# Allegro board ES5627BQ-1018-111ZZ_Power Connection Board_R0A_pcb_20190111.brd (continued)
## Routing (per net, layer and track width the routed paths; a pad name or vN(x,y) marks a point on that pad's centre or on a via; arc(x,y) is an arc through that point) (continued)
VMONITOR_3V3_EN: length 5.8
  TOP w0.127: R8.2 v2(84.75,29.54)
  TOP w0.381: R8.2 84.72,30.22 R7.2 C14.1 82.54,30.37 82.54,31.54 82.31,31.76 U1.7
  BOTTOM w0.127: v2(84.75,29.54) 85.06,29.23 v1(85.51,29.23)
VMONITOR_3V3_PG: length 8.7
  TOP w0.254: 79.07,30.79 79.07,28.73 CONN1.1 ; 79.07,30.79 R4.1 ; 79.07,30.79 79.56,30.79 81.18,32.41 U1.6
  BOTTOM w0.127: CONN1.1 78.39,28.53 v1(76.22,28.53)
VREG5_USB_VCC5P0: length 3.3
  TOP w0.254: U2.6 v2(74.48,40.38) 73.62,40.38 C41.1
  BOTTOM w0.127: v1(75.35,40.43) 74.53,40.43 v2(74.48,40.38)
VREG5_VSTB_3V3: length 6.6
  TOP w0.254: R4.2 C6.2 79.03,33.88 79.51,34.36 v2(80.43,34.36) U1.3
  BOTTOM w0.127: v2(80.43,34.36) 79.87,34.92 v1(79.87,35.48)
VSTB_3V3: length 18.7
  BOTTOM w0.381: C121.2 42.68,41.14 42.71,41.17 ; 40.65,41.24 40.6,41.19 C59.1 ; 41.67,41.34 41.69,41.32 C120.1
  BOTTOM w0.762: CONN20.18 41.35,50.88 ; CONN20.18 41.01,51.87 ; CONN20.18 40.01,49.55 ; CONN20.18 39.02,49.89 ; CONN20.18 41.01,49.89 ; 39.02,44.39 CONN20.6 ; CONN20.6 41.01,46.37 ; CONN20.6 40.01,46.71 ; CONN20.6 41.35,45.38 ; CONN20.6 40.01,44.05 ; CONN20.6 39.02,46.37 ; CONN20.6 41.01,44.39
  vias: v1(39.96,41.98)
VSTB_3V3_BODE: length 7.7
  TOP w0.127: v2(75.84,35.39) 75.84,35.71 76.12,35.99 R5.1
  TOP w0.254: U1.1 80.57,35.66 80.2,36.03 C9.1 R2.2 77.08,36.03 R5.1
  BOTTOM w0.127: v1(75.07,34.69) 75.14,34.69 v2(75.84,35.39)
VSTB_3V3_VIN: length 13.2
  TOP w0.381: R8.1 v2(86.6,30.24) ; C20.1 90.82,36.44 90.89,36.37 ; C19.1 89.77,36.29 89.8,36.26
  BOTTOM w0.381: v2(86.6,30.24) 86.6,35.02 v1(87.34,35.76) 87.56,35.98 v2(88.78,35.98) ; v2(93.04,35.44) 93.04,36.5 92.77,36.77 C22.1 92.09,36.77 91.82,36.5 v2(91.82,35.39)
N52288693: length 6.7
  TOP w0.254: U4.10 14.52,31.32 14.32,31.12 DB2.C 14.35,30.12 C91.1 v2(16.8,30.12) 17.5,30.12 D1.C
  BOTTOM w0.127: v2(16.8,30.12) 16.8,29.74 v1(16.44,29.38)
N55217970: length 5.1
  TOP w0.254: U7.3 v2(35.89,31.78)
  BOTTOM w0.127: v2(35.89,31.78) 35.55,31.44 v1(35.55,30.85)
  BOTTOM w0.254: v2(35.89,31.78) 36.64,31.78 R78.1 R79.1
N55218056: length 3
  TOP w0.254: U7.1 v2(36.83,33.68)
  BOTTOM w0.127: v1(36.83,34.56) v2(36.83,33.68)
  BOTTOM w0.254: C132.1 37.7,33.68 v2(36.83,33.68)
N55218105: length 2
  BOTTOM w0.127: v1(39.84,29.89) 39.86,29.91 R80.2
  BOTTOM w0.254: C133.2 R80.2
N55218124: length 4
  TOP w0.254: v2(41.59,31.74) 40.42,31.74 U7.4
  BOTTOM w0.127: v1(41.49,32.79) 41.59,32.68 v2(41.59,31.74)
  BOTTOM w0.254: R80.1 R81.1 v2(41.59,31.74)
N55219000: length 3.9
  TOP w0.254: U8.3 v2(73.45,26.7)
  BOTTOM w0.127: v1(73.95,27.35) 73.95,27.2 v2(73.45,26.7)
  BOTTOM w0.254: R84.1 72.65,26.92 R83.1 72.88,26.7 v2(73.45,26.7)
N55219084: length 3.5
  TOP w0.254: v2(73.47,24.73) 73.4,24.8 U8.1
  BOTTOM w0.127: v1(73.75,23.92) 73.75,24.45 v2(73.47,24.73)
  BOTTOM w0.254: v2(73.47,24.73) 73.4,24.8 72.39,24.8 C135.1
N55219133: length 2.1
  BOTTOM w0.127: v1(70.27,24.73) 70.37,24.83 C136.2
  BOTTOM w0.254: C136.2 70.34,25.8 R85.2
N55219143: length 4.1
  TOP w0.254: U8.4 v2(68.67,26.7)
  BOTTOM w0.127: v2(68.67,26.7) 68.27,26.7 v1(67.93,26.36)
  BOTTOM w0.254: R86.1 69.3,26.95 R85.1 69.31,26.7 v2(68.67,26.7)
N55250293: length 2.1
  BOTTOM w0.127: CB54.2 20.54,20.64 v1(20.64,20.54)
  BOTTOM w0.254: RB25.2 CB54.2

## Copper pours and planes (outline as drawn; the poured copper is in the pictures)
AGND_FPGA_1V2 on BOTTOM: 11.63,23.95 10.85,23.95 10.59,23.7 10.59,21.97 11.25,21.31 13.84,21.31 13.84,23.44 13.54,23.75 11.84,23.75
GND on TOP: 52.04,30.38 52.04,39.38 52.57,39.91 57.12,39.91 57.41,39.62 57.41,32.32 54.97,29.89 52.54,29.89
GND on TOP: 31.98,41.94 40.89,41.94 41.61,41.22 41.61,39.9 40.67,38.96 38.35,38.96 37.41,38.02 37.41,35.43 36.55,34.57 33.17,34.57 32.72,35.03 32.72,35.51 32.99,35.79 35.59,35.79 35.92,36.12 35.92,38.25 33.66,40.51 31.93,40.51 31.93,41.88
GND on TOP: 14.59,17.39 11.49,17.39 11.26,17.16 11.26,13.94 11.77,13.43 14.51,13.43 15.2,14.11 15.2,16.78
GND on TOP: 24.61,24.21 27.18,24.21 27.76,23.62 27.76,22.83 27.2,22.28 24.69,22.28 24.43,22.53 24.43,24.03
GND on TOP: 30.85,17.44 27.44,17.44 26.81,16.81 26.81,14.22 27.42,13.61 30.59,13.61 31.33,14.34 31.33,16.96
GND on TOP: 64.11,37.12 64.11,40.82 64.57,41.28 64.57,44.05 65.23,44.7 65.81,44.7 65.81,47.5 64.95,48.36 64.95,50.27 65.33,50.65 68.17,50.65 68.58,50.24 68.58,45.9 69.77,44.7 69.77,40.52 69.4,40.15 69.4,35.25 70.96,33.7 70.96,31.37 69.62,30.03 68.59,30.03 68.2,30.41 68.2,33.06 64.68,36.59 64.64,36.59
GND on TOP: 80.73,17.7 84.03,17.7 84.47,17.26 84.47,14.9 83.91,14.34 80.93,14.34 80.43,14.85 80.43,17.39
GND on TOP: 77.25,38.07 77.25,42.36 78.19,43.3 82.87,43.3 82.92,43.25 83.7,43.25 84.57,44.11 86.49,44.11 86.84,43.76 86.84,41.85 86.72,41.72 82.15,41.72 81.77,41.34 79.89,41.34 79.64,41.09 79.64,38.09 79.61,38.07
GND on TOP: 81.37,26.03 81.04,26.36 81.04,29.05 81.29,29.3 86.45,29.3 86.92,29.77 86.92,30.58 86.59,30.91 83.74,30.91 83.29,31.37 83.29,35.79 82.78,36.3 82.78,37.54 82.93,37.69 84.71,37.69 84.81,37.8 85.44,37.8 85.44,37.8 85.84,38.19 88.17,38.19 88.71,38.73 88.71,39.51 89.65,40.45 93.2,40.45 93.2,38.93 93.18,38.91 91.81,38.91 91.7,38.8 91.7,38.3 90.84,37.43 89.34,37.43 89.13,37.22 86.81,37.22 86.19,36.59 86.19,32.81 86.45,32.56 87.01,32.56 87.03,32.58 88.2,32.58 88.28,32.5 88.28,32.48 88.77,31.98 88.77,31.9 89.37,31.31 89.37,27.12 88.55,26.31 82.84,26.31 82.56,26.03
GND on TOP: 67.35,17.8 63.41,17.8 62.8,17.19 62.8,15.21 63.84,14.17 66.79,14.17 67.52,14.9 67.52,17.62
GND on TOP: 15.17,26.84 15.91,27.58 19.37,27.58 20.74,28.95 25.82,28.95 25.94,28.82 25.94,27.75 25.41,27.22 20.53,27.22 20.14,26.83 18.34,26.83 17.49,25.98 17.49,23.39 17.84,23.03 19.85,23.03 19.9,22.98 19.9,22.01 15.73,22.01 15.17,22.57
GND on BOTTOM: 76.77,37.91 76.77,37.91 76.77,36.43 77.14,36.07 78.66,36.07 79.92,37.32 79.92,42.69 79.07,43.54 77.06,43.54 76.77,43.24
GND on BOTTOM: 40.88,29.15 38.14,29.15 37.12,28.14 37.12,22.95 37.58,22.5 38.97,22.5 39.63,23.16 39.63,24.45 40.73,25.54 40.73,27.93 41.03,28.24 41.03,29
GND on BOTTOM: 65.54,19.7 63.76,19.7 63.18,19.12 63.18,15.18 64.15,14.22 66.91,14.22 67.17,14.47 67.17,15.31 66.53,15.94 66.53,16.93 65.75,17.72 65.75,19.5
GND on BOTTOM: 86.22,35.12 86.17,35.17 86.17,36.69 85.85,37.01 82.93,37.01 82.68,36.75 82.68,33.07 81.46,31.85 81.46,27.38 82.55,26.29 88.95,26.29 89.48,26.82 89.48,27.41 86.22,30.67
GND on BOTTOM: 57.97,28.56 55.45,28.56 54.95,28.07 54.95,21.75 55.52,21.19 56.65,21.19 57.99,22.53 57.99,26.85 57.99,27.38 58.15,27.54 58.15,28.39
GND on BOTTOM: 71.98,40.16 71.42,40.16 70.69,39.42 70.69,36.73 71.25,36.17 73.23,36.17 73.69,36.63 73.69,37.57 73.25,38 72.47,38 72.29,38.18 72.29,39.85
GND on BOTTOM: 34,39.84 44.03,39.84 45.12,38.74 45.12,36.69 40.62,32.2 36.24,32.2 35.52,32.92 35.52,34.53 33.8,36.25 33.8,39.63
GND on BOTTOM: 15.02,25.49 17.31,25.49 17.74,25.06 17.74,21.02 16.27,19.55 15.45,19.55 15.02,19.98
GND on BOTTOM: 23.61,36.49 26.81,36.49 26.93,36.37 26.93,33.34 26.83,33.24 23.73,33.24 23.62,33.35 22.23,33.35 22.02,33.55 22.02,36.14 22.37,36.49 23.61,36.49
GND on BOTTOM: 11.64,36.67 14.87,36.67 15,36.54 15,33.37 14.89,33.27 12.82,33.27 12.37,32.82 9.78,32.82 9.32,33.27 9.32,35.79 9.6,36.07 11.14,36.07 11.39,36.32 11.39,36.42
GND on V4, V5, V6, G7: 107.7,53.96 107.81,53.91 107.86,53.8 107.86,1.2 107.81,1.09 107.7,1.04 1.2,1.04 1.09,1.09 1.04,1.2 1.04,53.8 1.09,53.91 1.2,53.96
VCC12 on TOP: 50.79,31.62 50.79,33.39 49.9,34.28 49.9,38.63 54.37,43.1 54.37,51.83 53.22,52.98 46.82,52.98 45.91,52.06 45.91,39.8 45.25,39.14 45.25,34.13 44.44,33.32 43.75,33.32 43.27,32.83 43.27,31.31 44.28,30.29 45.32,30.29 45.55,30.07 45.55,28.59 45.71,28.44 49.11,28.44 50.3,29.63 50.3,31.13
VCC12 on BOTTOM: 53.07,52.29 47.31,52.29 46.37,51.35 46.37,42.05 46.38,42.04 45.58,41.24 45.58,35.48 43.19,33.09 43.19,32.5 45.04,30.65 45.12,30.65 45.65,30.12 45.65,29.99 50.02,29.99 53.73,33.7 53.73,51.53 53.78,51.58
VCC12 on V5: 54.37,51.83 53.22,52.98 46.82,52.98 45.91,52.06 45.91,40.73 45.25,40.07 45.25,34.13 44.44,33.32 43.75,33.32 43.27,32.83 43.27,31.31 44.28,30.29 51.46,30.29 54.37,33.2
VCC12 on V6: 54.37,51.83 53.22,52.98 46.82,52.98 45.91,52.06 45.91,40.73 45.25,40.07 45.25,34.13 44.44,33.32 43.75,33.32 43.27,32.83 43.27,31.31 44.28,30.29 45.32,30.29 45.37,30.24 51.84,30.24 54.37,32.77
CPLD_VDD1P8 on TOP: 13.14,40.02 10.17,40.02 9.99,40.2 9.99,41.19 10.78,41.98 15.66,41.98 17.61,43.93 17.61,44.75 17.54,44.82 17.54,47.06 18.58,48.1 24.04,48.1 24.6,48.68 25.13,49.19 25.13,53 24.2,53.94 13.67,53.94 9.48,49.75 9.48,47.77 7.44,45.73 7.44,40.06 6.11,38.73 6.11,37.15 7.1,36.16 11.62,36.16 12.13,36.67 13.24,36.67 13.4,36.82 13.4,39.77
CPLD_VDD1P8 on BOTTOM: 10.78,36.44 6.84,36.44 6.13,37.15 6.13,38.32 7.21,39.4 7.21,41.35 8.77,42.91 8.82,42.91 11.54,45.62 11.54,52.29 13.18,53.93 23.8,53.93 24.95,52.77 24.95,49.14 24.32,48.51 20.03,48.51 17.87,46.35 17.87,41.98 16.75,40.86 16.72,40.86 16.72,39.11 15.47,37.85 12.19,37.85
CPLD_VDD1P8_VIN on TOP: 8.01,29.76 8.01,33.04 8.82,33.85 12.48,33.85 13.4,32.94 13.4,31.92 13.09,31.62 13.09,29.99 12.94,29.84 9.26,29.84 9.23,29.86 9.05,29.86 8.75,29.56 8.21,29.56
FPGA_1V2 on TOP: 23.91,20.9 24.6,21.58 28.99,21.58 29.07,21.66 29.91,21.66 30.24,21.3 30.44,21.13 30.44,18.74 29.98,18.28 21.91,18.28 21.35,18.84 21.35,20.36 21.36,20.38 21.36,20.66 21.6,20.9
FPGA_1V2 on BOTTOM: 24.72,21.46 27.85,21.46 28.18,21.79 30.39,21.79 30.57,21.61 30.57,19.47 29.83,18.74 25.05,18.74 24.52,19.27 24.52,21.25
FPGA_1V2 on V5: 24.9,19.14 24.12,19.93 24.12,46.53 25.79,48.2 29.04,48.2 30.39,46.86 30.39,20.21 29.32,19.14
FPGA_1V2_SW on TOP: 19.9,24.33 18.45,24.33 18.4,24.27 18.4,23.46 18.45,23.41 19.92,23.41 20.33,23 20.33,22.8 20.76,22.37 23.35,22.37 23.58,22.6 23.58,23.74 23.07,24.25 19.97,24.25
FPGA_1V2_VIN on TOP: 20.91,26.43 18.5,26.43 18.32,26.26 18.32,25.49 18.48,25.34 19.97,25.34 20,25.37 20.76,25.37 21.14,24.96 21.52,24.6 27.04,24.6 27.39,24.96 27.39,25.6 27.21,25.77 26.76,25.77 26.73,25.75 26.1,25.75 25.64,26.21 21.55,26.21 21.3,26.46 20.94,26.46
FPGA_2V5 on TOP: 35.62,37.48 35.62,38.04 33.74,39.92 31.99,39.92 31.66,40.25 31.66,53.03 30.74,53.94 26.73,53.94 25.99,53.21 25.99,48.56 27.95,46.6 27.95,39.01 29.58,37.38 35.52,37.38
FPGA_2V5 on BOTTOM: 32.45,36.75 32.45,34.74 33.21,33.98 34.35,33.98 35.01,33.32 35.01,32.2 34.5,31.69 32.32,31.69 30.62,33.39 30.62,37.91 30.36,38.17 30.36,39.08 30.64,39.36 33.06,39.36 33.41,39.01 33.41,37.71
FPGA_2V5_IN on TOP: 42.99,38.4 37.93,38.4 37.7,38.17 37.7,37.38 37.73,37.36 40.07,37.36 40.09,37.33 42.83,37.33 43.11,37.61 43.11,38.27
HEATER_VCC12 on TOP: 87.27,40.56 87.27,42.65 87.68,43.05 90.3,43.05 90.55,42.8 90.55,41.91 89.13,40.49 87.35,40.49
HEATER_VCC12 on TOP: 26.62,26.73 26.62,27.85 26.79,28.01 29.51,28.01 30,27.53 30,26.68 29.51,26.2 26.91,26.2 26.61,26.5 26.61,26.72
HEATER_VCC12 on TOP: 62.67,47.21 59.8,47.21 58.35,45.76 58.35,33.44 57.8,32.89 57.8,31.39 58.66,30.52 62.42,30.52 63.33,29.61 63.33,27.83 63.49,27.68 66.63,27.68 66.86,27.91 66.86,29.3 66.56,29.61 66.56,33.32 63.1,36.77 63.1,46.78 62.9,46.96
HEATER_VCC12 on TOP: 96.14,39.29 94.41,39.29 93.88,38.76 93.88,37.64 94.11,37.41 94.82,37.41 95.12,37.72 96.14,37.72 96.52,38.1 96.52,38.91
HEATER_VCC12 on BOTTOM: 62.67,47.21 59.8,47.21 58.35,45.76 58.35,33.44 57.8,32.89 57.8,31.39 58.66,30.52 66.23,30.52 66.56,30.85 66.56,33.32 63.1,36.77 63.1,46.78 62.9,46.96
HEATER_VCC12 on S3: 64.82,32.95 65.17,32.6 65.17,31.05 60.02,25.9 59.98,25.9 54.18,20.09 35.48,20.09 35.13,20.45 35.13,20.62 34.49,21.26 30.54,21.26 27.1,24.7 27.1,27.15 29.09,29.14 37.7,29.14 41.86,33.3 64.59,33.3 64.82,33.07
HEATER_VCC12 on V5: 59.8,47.21 58.35,45.76 58.35,33.44 57.8,32.89 57.8,31.39 58.66,30.52 66.2,30.52 66.86,31.18 66.86,45.28 64.93,47.21
HEATER_VCC12 on V6: 59.8,47.21 58.35,45.76 58.35,33.44 57.8,32.89 57.8,31.39 57.31,30.9 57.31,30.13 57.87,29.58 65.9,29.58 66.56,30.24 66.56,32.56 69.96,35.96 79.28,35.96 79.56,35.68 94.73,35.68 96.7,37.65 96.7,39.19 96.44,39.45 96.13,39.45 88.36,47.21
LGND_USB_VCC5P0 on BOTTOM: 70,39.8 70,41.05 70.33,41.38 72.44,41.38 74.02,39.8 75.54,39.8 75.84,39.5 75.84,39.12 75.59,38.86 75.13,38.86 74.37,38.1 74.37,38.07 73.56,38.07 73.33,38.3 73.33,39.47 72.52,40.28 71.12,40.28 70.59,39.75 70.59,39.7 70.1,39.7
LGND_VSTB_3V3 on BOTTOM: 81.94,34.19 81.51,34.19 80.34,33.02 79.22,33.02 78.23,32.03 78.23,30.78 79.17,29.84 79.93,29.84 80.42,30.33 80.42,31.65 82.12,33.35 82.19,33.35 82.22,33.38 82.22,33.91
MANG_1P2 on TOP: 25.41,39.92 22.67,39.92 22.41,40.18 22.41,41.24 23.28,42.11 24.37,42.11 25.36,43.1 25.36,46.86 24.72,47.49 21.02,47.49 20.46,46.93 20.46,43.63 19.21,42.38 19.21,38.8 22.03,35.98 23.07,35.98 23.89,36.8 25.44,36.8 25.44,39.9
MANG_1P2 on BOTTOM: 20.72,45.37 19.87,44.52 19.87,37.71 20.64,36.95 23.56,36.95 23.56,38.88 23.4,39.03 23.4,40.23 25.51,42.33 25.51,46.86 24.52,47.85 21.45,47.85 20.72,47.12
MANG_1P2_VIN on TOP: 24.62,33.77 21.7,33.77 21.4,33.47 21.4,31.16 21.93,30.62 25.13,30.62 25.49,30.98 25.49,32.91
MANG_1P2_VIN on BOTTOM: 23.2,33.11 20.97,33.11 20.28,32.43 20.28,29.96 20.64,29.61 21.42,29.61 21.8,29.99 24.29,29.99 24.29,32.02
PSU_VCC12 on TOP: 1.59,7.94 1.59,9.9 2.53,10.84 14.01,10.84 16.6,13.43 16.6,16.88 17.54,17.82 25.54,17.82 26.4,16.96 26.4,8.32 25.21,7.13 2.4,7.13
PSU_VCC12 on TOP: 36.15,30.17 34.05,30.17 34,30.12 33.13,30.12 31.96,28.95 31.96,22.5 32.32,22.14 34.07,22.14 34.25,21.96 35.8,21.96 36.36,22.52 36.36,29.96
PSU_VCC12 on TOP: 54.21,28.92 51.09,28.92 50.3,28.14 50.3,21.63 50.71,21.23 51.32,21.23 51.39,21.3 51.62,21.3 52.11,20.82 52.11,19.96 52.39,19.68 54.09,19.68 54.32,19.91 54.32,28.82
PSU_VCC12 on TOP: 68.34,14.9 67.04,13.61 65.14,13.61 63.64,12.11 63.64,7.76 64.32,7.08 87.26,7.08 88.33,8.15 88.33,10.43 85.25,13.51 80.48,13.51 79.28,14.7 79.28,17.59 75.12,21.76 71.03,21.76 68.34,19.07
PSU_VCC12 on BOTTOM: 20.74,18.08 17.23,18.08 14.45,15.3 14.45,14.03 12.89,12.46 3.85,12.46 2.02,10.63 2.02,7.82 2.55,7.28 25.66,7.28 26.45,8.07 26.45,16.96 25.23,18.18 24.12,18.18 23.71,18.59 23.71,18.94 23.53,19.12 21.78,19.12
PSU_VCC12 on BOTTOM: 62.93,13.28 62.93,8.25 63.79,7.38 87.62,7.38 88.91,8.68 88.91,10.03 88.22,10.71 88.2,10.71 85.94,12.97 82.54,12.97 81.65,13.86 81.65,16.98 76.9,21.73 69.02,21.73 66.69,19.4 66.69,17.49 66.99,17.19 67.4,17.19 67.52,17.06 67.52,14.32 66.99,13.78 63.43,13.78
PSU_VCC12 on S3: 25.97,17.54 16.19,17.54 15.25,16.6 15.25,13.94 13.78,12.46 2.5,12.46 1.48,11.45 1.48,8.07 2.12,7.43 25.64,7.43 26.68,8.48 26.68,16.83
PSU_VCC12 on S3: 83.75,15.36 64.78,15.36 63.87,14.44 63.87,7.71 65.06,6.52 87.28,6.52 88.68,7.92 88.68,10.43
PSU_VCC12 on V5: 31.86,28.54 31.86,28.52 30.95,27.6 30.95,20.01 29.73,18.79 17.05,18.79 15.71,17.44 15.71,11.75 17.63,9.83 26.67,9.83 26.86,9.64 97.06,9.64 98.56,11.14 98.56,21.6 85.37,34.79 69.89,34.79 67.54,32.44 67.54,30.8 66.5,29.77 43.93,29.77 42.66,31.04 42.66,34.13 42,34.79 38.11,34.79
PSU_VCC12 on V6: 17.33,10.36 16.14,11.55 16.14,23.51 22.15,29.53 54.52,29.53 55.05,29 89.06,29 96.64,21.42 96.64,12.29 95.02,10.66 63.15,10.66 60.92,8.43 58.13,8.43 57.2,9.35 48.43,9.35 47.36,8.27 44.97,8.27 43.19,10.05 26.71,10.05 26.4,10.36
SCREW1 on TOP (solid shape): outline of 235 points within 1.5,45.74 8.5,52.74
SCREW1 on BOTTOM (solid shape): outline of 235 points within 1.5,45.74 8.5,52.74
SCREW2 on TOP (solid shape): outline of 228 points within 100.4,13.24 107.4,20.24
SCREW2 on BOTTOM (solid shape): outline of 228 points within 100.4,13.24 107.4,20.24
SCREW3 on TOP (solid shape): outline of 228 points within 1.5,13.24 8.5,20.24
SCREW3 on BOTTOM (solid shape): outline of 228 points within 1.5,13.24 8.5,20.24
SCREW4 on TOP (solid shape): outline of 235 points within 50.4,3.74 57.4,10.74
SCREW4 on BOTTOM (solid shape): outline of 235 points within 50.4,3.74 57.4,10.74
SCREW5 on TOP (solid shape): outline of 235 points within 90.24,45.74 97.24,52.74
SCREW5 on BOTTOM (solid shape): outline of 235 points within 90.24,45.74 97.24,52.74
SENSE_12V_HEATER on TOP: 61.3,29.23 58.68,29.23 57.97,28.52 57.97,19.98 58.79,19.17 65.69,19.17 67.65,21.13 67.65,26.46 67.02,27.09 66.18,27.09 66.13,27.04 62.14,27.04 61.53,27.65 61.53,29
SENSE_12V_HEATER on BOTTOM: 58.79,28.52 65.54,28.52 67.14,26.92 67.14,22.85 65.69,21.4 59.8,21.4 58.68,22.52 58.68,27.22 58.51,27.4 58.51,28.24
SENSE_12V_PSU on TOP: 49.11,27.91 44.31,27.91 43.11,29.1 43.11,30.04 42.68,30.47 40.32,30.47 40.07,30.22 40.07,21.68 40.65,21.1 48.58,21.1 49.31,21.84 49.31,27.7
SENSE_12V_PSU on BOTTOM: 41.59,29.23 48.52,29.23 49.69,28.06 49.69,23.94 48.58,22.83 41.08,22.83 40.85,23.06 40.85,24.88 41.46,25.49 41.46,29.1
SENSE_12V_PSU on S3: 49.11,27.91 44.31,27.91 43.74,28.47 42.19,28.47 40.07,26.35 40.07,22.58 41.07,21.58 49.06,21.58 49.31,21.84 49.31,27.7
SW_USB_VCC5P0 on TOP: 80.91,49.32 83.04,49.32 84.16,48.2 84.16,46.12 83.37,45.33 80.73,45.33 80.27,45.79 80.27,48.68
SW_USB_VCC5P0 on TOP: 80.27,40.99 82,40.99 82.18,41.17 82.94,41.17 83.08,41.31 83.91,41.31 84.11,41.1 84.11,40.58 83.6,40.07 80.17,40.07 80.17,40.89
SW_USB_VCC5P0 on BOTTOM: 80.6,46.12 83.58,46.12 84.29,45.41 84.29,40.56 83.88,40.15 82.36,40.15 80.45,42.05 80.45,45.97
SW_VSTB_3V3 on TOP: 94.73,34.38 89.95,34.38 89.47,33.9 86.95,33.9 86.8,33.75 86.8,32.89 86.88,32.81 88.53,32.81 91.17,30.17 94.02,30.17 94.8,30.95 94.8,34.31
USB_VCC5P0 on TOP: 72.83,51.3 74.6,51.3 74.77,51.13 74.78,51.13 74.8,51.1 74.8,49.35 75.11,49.05 76.45,49.05 76.67,48.83 76.67,45.9 76.13,45.36 75.11,45.36 74.8,45.06 74.8,43.91 74.45,43.55 70.95,43.55 70.29,44.21 70.29,46.37 69.76,46.91 69.76,53.46 69.91,53.61 71.69,53.61 72.22,53.08 72.22,51.91
USB_VCC5P0 on S3: 72.02,53.59 24.57,53.59 10.7,39.72 10.7,28.49 12.86,26.33 25.26,26.33 27.24,28.31 27.24,29.29 26.51,30.01 13.94,30.01 13.09,30.86 13.09,33.59 21.69,42.19 71.33,42.19 73.54,44.4 73.54,52.06
USB_VCC5P0_VIN on TOP: 85.2,40.4 86.55,40.4 87.16,39.79 88.07,39.79 88.5,39.36 88.5,39.01 87.95,38.45 80.35,38.45 80.05,38.75 80.05,39.44 80.25,39.64 84.44,39.64
VMONITOR_3V3 on TOP: 45.06,39.57 45.06,40.54 44.58,41.02 42.7,41.02 42.09,40.41 42.09,39.19 42.24,39.04 43.03,39.04 43.36,39.37 44.86,39.37
VMONITOR_3V3 on TOP: 6.86,31.5 5.44,31.5 5.31,31.37 5.31,28.57 5.64,28.24 6.96,28.24 7.34,28.63 7.34,31.01
VMONITOR_3V3 on TOP: 94.24,26.05 91.68,26.05 90.97,25.34 82.48,25.34 82.46,25.37 77.4,25.37 76.9,24.86 76.9,22.93 77.73,22.09 79.77,22.09 80.07,22.4 82.13,22.4 82.28,22.24 82.28,21.66 82.59,21.35 94.07,21.35 94.93,22.22 94.93,25.37
VMONITOR_3V3 on BOTTOM: 36.69,46.68 34.83,46.68 33.92,45.76 33.92,40.71 34.33,40.3 36.48,40.3 37.2,41.01 37.2,46.17
VMONITOR_3V3 on BOTTOM: 18.49,31.67 17.81,31.67 17.45,31.32 17.45,29.84 17.96,29.34 19.3,29.34 19.53,29.57 19.53,30.78 19.02,31.29 18.87,31.29
VMONITOR_3V3 on BOTTOM: 88.48,25.32 77.46,25.32 76.95,24.81 76.95,22.9 78.22,21.63 89.22,21.63 89.49,21.91 89.49,24.3
VMONITOR_3V3 on V4: 107.66,16.91 107.66,46.98 101.69,52.95 11.75,52.95 9.28,50.49 9.28,42.66 5.6,38.98 5.6,14.85 9.41,11.04 36.92,11.04 37.25,10.71 37.25,7.79 39.43,5.61 41.59,5.61 43.95,7.97 43.95,10.38 44.61,11.04 101.79,11.04
VSTB_3V3 on BOTTOM: 38.8,40.12 38.8,51.86 39.08,52.14 41.79,52.14 42.43,51.5 42.43,42.18 43.04,41.57 43.04,40.48 42.86,40.3 39.99,40.3 39.66,39.97 38.95,39.97
VSTB_3V3_VIN on TOP: 86.8,36.42 86.8,34.99 86.98,34.82 94.19,34.82 94.96,35.58 94.96,36.59 94.75,36.8 93.94,36.8 93.25,37.48 93.25,37.58 91.45,37.58 90.76,36.9 87.28,36.9

Small or netless copper shapes (teardrops, artwork), in the pictures only: 1 on G2

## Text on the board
Ref Des/Assembly Top: P\N:142000002196H REV:0A
DISPLAY_TOP: 24 | 12 | 13 | 20 | 2 | 19 | This document and the | technical data disclosed | are proprietary to Accton | Tech. Corp. and shall not be | duplicated, used, released, | or disclosed without | expressed written permission. | LinJing | 20181218 | 1 | 0.2 | ZONE | ROUGHNESS | ANGLE | PART NO. | MATERIAL | DESIGN | SCALE | UNIT | DIM. | 500 | 250 | 63 | 16 | 0 | GRADE | 1000 | 0.1 | 0.05 | . | 0.15 | 0.25 | 0.3 | 0.5 | 3 | 0.4 | 0.6 | 0.8 | 4 | 1.2 | 5 | 1.8 | 3.0 | FINISH. | MM | [IN] | OUTLINE-Corient_psu-pcb | Reason | DESCRIPTION | UNSPECIFIED | TOL'S (+/-   mm) | DWG. TITLE | SHEET  / | REV. | SIZE | FMA-MD01001-02 R02 | 1deg | +/- | TECHNOLOGY CORP. | PCB T=2.5mm | A0 | A3 | 55 [2.165] | limit height7.6 [0.299] | 108.9 [4.287] | 2.5 [0.098] | dia7 [dia0.276] | dia3 [dia0.118] | dia3.5 [dia0.138] | dia9 [dia0.354]
DISPLAY_BOTTOM: TOP (COMPONENT_SIDE)                      1
PAGE_OUTLINE: G2 (GND_LAYER_2)                          2
User.5: S5 (SIGNAL_LAYER_5)                       5
User.6: BOT (SOLDER_SIDE)                         8
User.7: SST (SILKSCREEN_TOP)                      9
User.8: SSB (SILKSCREEN_BOTTOM)                   10
User.9: SMT (SOLDER_MASK_TOP)                     11
User.10: SMB (SOLDER_MASK_BOTTOM)                  12
User.11: DRILL(FINISH HOLE SIZE LIST)                  15
User.12: PMT (PASTE_MASK_TOP)                     13
User.13: PMB (PASTE_MASK_BOTTOM)                  14
User.14: DIM (BOARD_DIMENSION)                    16
User.15: S3 (SIGNAL_LAYER_3)                       3
User.16: V4(VCC_LAYER_4 )                         4
User.17: S6(SIGNAL-LAYER_6)                        6
User.18: G7 | 7
User.19: S8(SIGNAL_LAYER_8)                          8
User.20: G9(GND_LAYER_9)                           9
User.21: V5 | 5
User.22: V6 | 6
User.27: FIGURE | SIZE | 10.0 | 12.0 | 30.0 | 40.0 | 43.0 | 71.0 | 118.0 | 138.0 | DRILL CHART: TOP to BOTTOM | ALL UNITS ARE IN MILS | TOLERANCE | +3.0/-3.0 | +2.0/-2.0 | PLATED | NON-PLATED | QTY | 25 | 720 | 48 | 14 | 40 | 24 | 2 | 3
